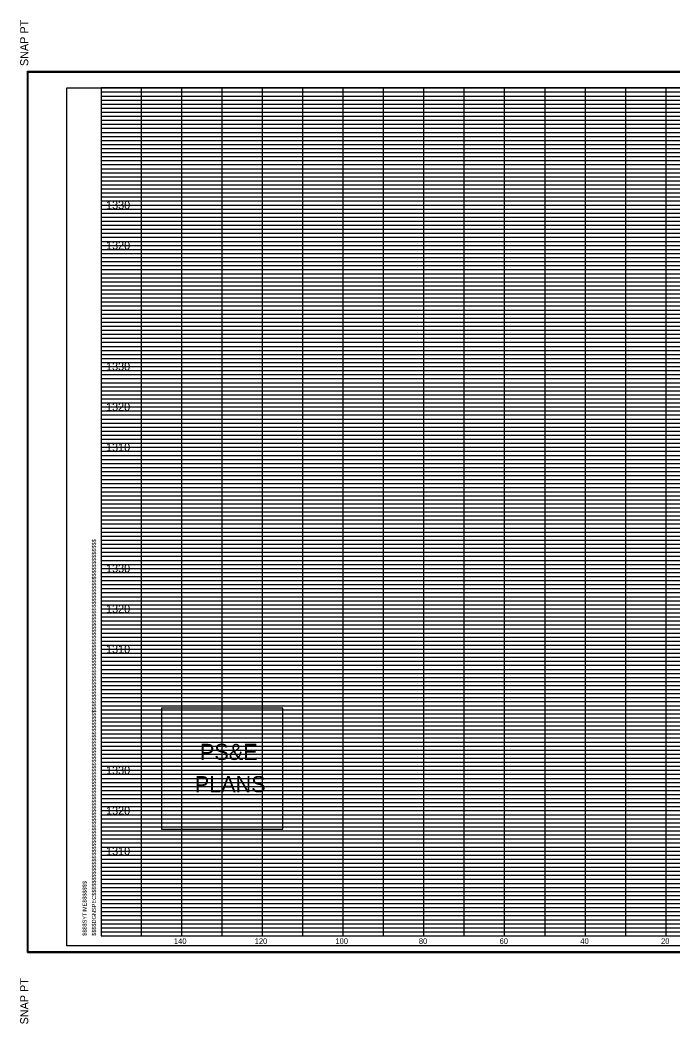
# Model space of a CAD drawing. Extents: x 980 to 1324, y 978 to 1227.
# Drawn here: x 979.9 to 1141.7, y 978.2 to 1226.8 of the extents above; entities that cross this region are included whole.
import ezdxf

# ---------------------------------------------------------------- set-up
doc = ezdxf.new("R2010")
doc.units = 0
for name, color, linetype in [('DESIGN - SHEET - Corner Text', 7, 'Continuous'), ('DESIGN - SHEET - Light Grid', 7, 'Continuous'), ('DESIGN - SHEET - Linework', 7, 'Continuous'), ('DESIGN - SHEET - Plot Shape', 7, 'Continuous'), ('DESIGN - TYPICAL - Finished Grade and Subgrade', 7, 'Continuous')]:
    doc.layers.add(name, color=color, linetype=linetype)

# ---------------------------------------------------------------- blocks, each defined once
blk = doc.blocks.new('XSTSHT')
at = {"layer": 'DESIGN - SHEET - Light Grid'}
for p, q in [((0, 20.9), (8, 20.9)), ((8, 20.9), (16, 20.9)), ((0, 20.8), (8, 20.8)), ((0, 20.7), (8, 20.7)), ((8, 20.8), (16, 20.8)), ((8, 20.7), (16, 20.7)), ((0, 20.6), (8, 20.6)), ((0, 20.5), (8, 20.5)), ((0, 20.4), (8, 20.4)), ((8, 20.6), (16, 20.6)), ((8, 20.5), (16, 20.5)), ((8, 20.4), (16, 20.4)), ((0, 20.3), (8, 20.3)), ((0, 20.2), (8, 20.2)), ((8, 20.3), (16, 20.3)), ((8, 20.2), (16, 20.2)), ((0, 20.1), (8, 20.1)), ((0, 19.9), (8, 19.9)), ((8, 20.1), (16, 20.1)), ((8, 19.9), (16, 19.9)), ((0, 19.8), (8, 19.8)), ((0, 19.7), (8, 19.7)), ((8, 19.8), (16, 19.8)), ((8, 19.7), (16, 19.7)), ((0, 19.6), (8, 19.6)), ((0, 19.5), (8, 19.5)), ((0, 19.4), (8, 19.4)), ((8, 19.6), (16, 19.6)), ((8, 19.5), (16, 19.5)), ((8, 19.4), (16, 19.4)), ((0, 19.3), (8, 19.3)), ((0, 19.2), (8, 19.2)), ((8, 19.3), (16, 19.3)), ((8, 19.2), (16, 19.2)), ((0, 19.1), (8, 19.1)), ((0, 18.9), (8, 18.9)), ((8, 19.1), (16, 19.1)), ((8, 18.9), (16, 18.9)), ((0, 18.8), (8, 18.8)), ((0, 18.7), (8, 18.7)), ((8, 18.8), (16, 18.8)), ((8, 18.7), (16, 18.7)), ((0, 18.6), (8, 18.6)), ((0, 18.5), (8, 18.5)), ((0, 18.4), (8, 18.4)), ((8, 18.6), (16, 18.6)), ((8, 18.5), (16, 18.5)), ((8, 18.4), (16, 18.4)), ((0, 18.3), (8, 18.3)), ((0, 18.2), (8, 18.2)), ((8, 18.3), (16, 18.3)), ((8, 18.2), (16, 18.2)), ((0, 18.1), (8, 18.1)), ((8, 18.1), (16, 18.1)), ((0, 17.9), (8, 17.9)), ((0, 17.8), (8, 17.8)), ((0, 17.7), (8, 17.7)), ((8, 17.9), (16, 17.9)), ((8, 17.8), (16, 17.8)), ((8, 17.7), (16, 17.7)), ((0, 17.6), (8, 17.6)), ((0, 17.5), (8, 17.5)), ((8, 17.6), (16, 17.6)), ((8, 17.5), (16, 17.5)), ((0, 17.4), (8, 17.4)), ((0, 17.3), (8, 17.3)), ((0, 17.2), (8, 17.2)), ((8, 17.4), (16, 17.4)), ((8, 17.3), (16, 17.3)), ((8, 17.2), (16, 17.2)), ((0, 17.1), (8, 17.1)), ((8, 17.1), (16, 17.1)), ((0, 16.9), (8, 16.9)), ((0, 16.8), (8, 16.8)), ((0, 16.7), (8, 16.7)), ((8, 16.9), (16, 16.9)), ((8, 16.8), (16, 16.8)), ((8, 16.7), (16, 16.7)), ((0, 16.6), (8, 16.6)), ((0, 16.5), (8, 16.5)), ((8, 16.6), (16, 16.6)), ((8, 16.5), (16, 16.5)), ((0, 16.4), (8, 16.4)), ((0, 16.3), (8, 16.3)), ((0, 16.2), (8, 16.2)), ((8, 16.4), (16, 16.4)), ((8, 16.3), (16, 16.3)), ((8, 16.2), (16, 16.2)), ((0, 16.1), (8, 16.1)), ((8, 16.1), (16, 16.1)), ((0, 15.9), (8, 15.9)), ((0, 15.8), (8, 15.8)), ((0, 15.7), (8, 15.7)), ((8, 15.9), (16, 15.9)), ((8, 15.8), (16, 15.8)), ((8, 15.7), (16, 15.7)), ((0, 15.6), (8, 15.6)), ((0, 15.5), (8, 15.5)), ((8, 15.6), (16, 15.6)), ((8, 15.5), (16, 15.5)), ((0, 15.4), (8, 15.4)), ((0, 15.3), (8, 15.3)), ((0, 15.2), (8, 15.2)), ((8, 15.4), (16, 15.4)), ((8, 15.3), (16, 15.3)), ((8, 15.2), (16, 15.2)), ((0, 15.1), (8, 15.1)), ((8, 15.1), (16, 15.1)), ((0, 14.9), (8, 14.9)), ((0, 14.8), (8, 14.8)), ((0, 14.7), (8, 14.7)), ((8, 14.9), (16, 14.9)), ((8, 14.8), (16, 14.8)), ((8, 14.7), (16, 14.7)), ((0, 14.6), (8, 14.6)), ((0, 14.5), (8, 14.5)), ((8, 14.6), (16, 14.6)), ((8, 14.5), (16, 14.5)), ((0, 14.4), (8, 14.4)), ((0, 14.3), (8, 14.3)), ((0, 14.2), (8, 14.2)), ((8, 14.4), (16, 14.4)), ((8, 14.3), (16, 14.3)), ((8, 14.2), (16, 14.2)), ((0, 14.1), (8, 14.1)), ((8, 14.1), (16, 14.1)), ((0, 13.9), (8, 13.9)), ((0, 13.8), (8, 13.8)), ((0, 13.7), (8, 13.7)), ((8, 13.9), (16, 13.9)), ((8, 13.8), (16, 13.8)), ((8, 13.7), (16, 13.7)), ((0, 13.6), (8, 13.6)), ((0, 13.5), (8, 13.5)), ((8, 13.6), (16, 13.6)), ((8, 13.5), (16, 13.5)), ((0, 13.4), (8, 13.4)), ((0, 13.3), (8, 13.3)), ((0, 13.2), (8, 13.2)), ((8, 13.4), (16, 13.4)), ((8, 13.3), (16, 13.3)), ((8, 13.2), (16, 13.2)), ((0, 13.1), (8, 13.1)), ((8, 13.1), (16, 13.1)), ((0, 12.9), (8, 12.9)), ((0, 12.8), (8, 12.8)), ((0, 12.7), (8, 12.7)), ((8, 12.9), (16, 12.9)), ((8, 12.8), (16, 12.8)), ((8, 12.7), (16, 12.7)), ((0, 12.6), (8, 12.6)), ((0, 12.5), (8, 12.5)), ((8, 12.6), (16, 12.6)), ((8, 12.5), (16, 12.5)), ((0, 12.4), (8, 12.4)), ((0, 12.3), (8, 12.3)), ((0, 12.2), (8, 12.2)), ((8, 12.4), (16, 12.4)), ((8, 12.3), (16, 12.3)), ((8, 12.2), (16, 12.2)), ((0, 12.1), (8, 12.1)), ((8, 12.1), (16, 12.1)), ((0, 11.9), (8, 11.9)), ((0, 11.8), (8, 11.8)), ((0, 11.7), (8, 11.7)), ((8, 11.9), (16, 11.9)), ((8, 11.8), (16, 11.8)), ((8, 11.7), (16, 11.7)), ((0, 11.6), (8, 11.6)), ((0, 11.5), (8, 11.5)), ((8, 11.6), (16, 11.6)), ((8, 11.5), (16, 11.5)), ((0, 11.4), (8, 11.4)), ((0, 11.3), (8, 11.3)), ((0, 11.2), (8, 11.2)), ((8, 11.4), (16, 11.4)), ((8, 11.3), (16, 11.3)), ((8, 11.2), (16, 11.2)), ((0, 11.1), (8, 11.1)), ((8, 11.1), (16, 11.1)), ((0, 10.9), (8, 10.9)), ((0, 10.8), (8, 10.8)), ((0, 10.7), (8, 10.7)), ((8, 10.9), (16, 10.9)), ((8, 10.8), (16, 10.8)), ((8, 10.7), (16, 10.7)), ((0, 10.6), (8, 10.6)), ((0, 10.5), (8, 10.5)), ((8, 10.6), (16, 10.6)), ((8, 10.5), (16, 10.5)), ((0, 10.4), (8, 10.4)), ((0, 10.3), (8, 10.3)), ((0, 10.2), (8, 10.2)), ((8, 10.4), (16, 10.4)), ((8, 10.3), (16, 10.3)), ((8, 10.2), (16, 10.2)), ((0, 10.1), (8, 10.1)), ((8, 10.1), (16, 10.1)), ((0, 9.9), (8, 9.9)), ((0, 9.8), (8, 9.8)), ((0, 9.7), (8, 9.7)), ((8, 9.9), (16, 9.9)), ((8, 9.8), (16, 9.8)), ((8, 9.7), (16, 9.7)), ((0, 9.6), (8, 9.6)), ((0, 9.5), (8, 9.5)), ((8, 9.6), (16, 9.6)), ((8, 9.5), (16, 9.5)), ((0, 9.4), (8, 9.4)), ((0, 9.3), (8, 9.3)), ((0, 9.2), (8, 9.2)), ((8, 9.4), (16, 9.4)), ((8, 9.3), (16, 9.3)), ((8, 9.2), (16, 9.2)), ((0, 9.1), (8, 9.1)), ((8, 9.1), (16, 9.1)), ((0, 8.9), (8, 8.9)), ((0, 8.8), (8, 8.8)), ((8, 8.9), (16, 8.9)), ((8, 8.8), (16, 8.8)), ((0, 8.7), (8, 8.7)), ((0, 8.6), (8, 8.6)), ((0, 8.5), (8, 8.5)), ((8, 8.7), (16, 8.7)), ((8, 8.6), (16, 8.6)), ((8, 8.5), (16, 8.5)), ((0, 8.4), (8, 8.4)), ((0, 8.3), (8, 8.3)), ((8, 8.4), (16, 8.4)), ((8, 8.3), (16, 8.3)), ((0, 8.2), (8, 8.2)), ((0, 8.1), (8, 8.1)), ((8, 8.2), (16, 8.2)), ((8, 8.1), (16, 8.1)), ((0, 7.9), (8, 7.9)), ((0, 7.8), (8, 7.8)), ((8, 7.9), (16, 7.9)), ((8, 7.8), (16, 7.8)), ((0, 7.7), (8, 7.7)), ((0, 7.6), (8, 7.6)), ((0, 7.5), (8, 7.5)), ((8, 7.7), (16, 7.7)), ((8, 7.6), (16, 7.6)), ((8, 7.5), (16, 7.5)), ((0, 7.4), (8, 7.4)), ((0, 7.3), (8, 7.3)), ((8, 7.4), (16, 7.4)), ((8, 7.3), (16, 7.3)), ((0, 7.2), (8, 7.2)), ((0, 7.1), (8, 7.1)), ((8, 7.2), (16, 7.2)), ((8, 7.1), (16, 7.1)), ((0, 6.9), (8, 6.9)), ((0, 6.8), (8, 6.8)), ((8, 6.9), (16, 6.9)), ((8, 6.8), (16, 6.8)), ((0, 6.7), (8, 6.7)), ((0, 6.6), (8, 6.6)), ((0, 6.5), (8, 6.5)), ((8, 6.7), (16, 6.7)), ((8, 6.6), (16, 6.6)), ((8, 6.5), (16, 6.5)), ((0, 6.4), (8, 6.4)), ((0, 6.3), (8, 6.3)), ((8, 6.4), (16, 6.4)), ((8, 6.3), (16, 6.3)), ((0, 6.2), (8, 6.2)), ((0, 6.1), (8, 6.1)), ((8, 6.2), (16, 6.2)), ((8, 6.1), (16, 6.1)), ((0, 5.9), (8, 5.9)), ((0, 5.8), (8, 5.8)), ((8, 5.9), (16, 5.9)), ((8, 5.8), (16, 5.8)), ((0, 5.7), (8, 5.7)), ((0, 5.6), (8, 5.6)), ((0, 5.5), (8, 5.5)), ((8, 5.7), (16, 5.7)), ((8, 5.6), (16, 5.6)), ((8, 5.5), (16, 5.5)), ((0, 5.4), (8, 5.4)), ((0, 5.3), (8, 5.3)), ((8, 5.4), (16, 5.4)), ((8, 5.3), (16, 5.3)), ((0, 5.2), (8, 5.2)), ((0, 5.1), (8, 5.1)), ((8, 5.2), (16, 5.2)), ((8, 5.1), (16, 5.1)), ((0, 4.9), (8, 4.9)), ((0, 4.8), (8, 4.8)), ((8, 4.9), (16, 4.9)), ((8, 4.8), (16, 4.8)), ((0, 4.7), (8, 4.7)), ((0, 4.6), (8, 4.6)), ((0, 4.5), (8, 4.5)), ((8, 4.7), (16, 4.7)), ((8, 4.6), (16, 4.6)), ((8, 4.5), (16, 4.5)), ((0, 4.4), (8, 4.4)), ((0, 4.3), (8, 4.3)), ((8, 4.4), (16, 4.4)), ((8, 4.3), (16, 4.3)), ((0, 4.2), (8, 4.2)), ((0, 4.1), (8, 4.1)), ((8, 4.2), (16, 4.2)), ((8, 4.1), (16, 4.1)), ((0, 3.9), (8, 3.9)), ((0, 3.8), (8, 3.8)), ((8, 3.9), (16, 3.9)), ((8, 3.8), (16, 3.8)), ((0, 3.7), (8, 3.7)), ((0, 3.6), (8, 3.6)), ((0, 3.5), (8, 3.5)), ((8, 3.7), (16, 3.7)), ((8, 3.6), (16, 3.6)), ((8, 3.5), (16, 3.5)), ((0, 3.4), (8, 3.4)), ((0, 3.3), (8, 3.3)), ((8, 3.4), (16, 3.4)), ((8, 3.3), (16, 3.3)), ((0, 3.2), (8, 3.2)), ((0, 3.1), (8, 3.1)), ((8, 3.2), (16, 3.2)), ((8, 3.1), (16, 3.1)), ((0, 2.9), (8, 2.9)), ((0, 2.8), (8, 2.8)), ((8, 2.9), (16, 2.9)), ((8, 2.8), (16, 2.8)), ((0, 2.7), (8, 2.7)), ((0, 2.6), (8, 2.6)), ((0, 2.5), (8, 2.5)), ((8, 2.7), (16, 2.7)), ((8, 2.6), (16, 2.6)), ((8, 2.5), (16, 2.5)), ((0, 2.4), (8, 2.4)), ((0, 2.3), (8, 2.3)), ((8, 2.4), (16, 2.4)), ((8, 2.3), (16, 2.3)), ((0, 2.2), (8, 2.2)), ((0, 2.1), (8, 2.1)), ((8, 2.2), (16, 2.2)), ((8, 2.1), (16, 2.1)), ((0, 1.9), (8, 1.9)), ((0, 1.8), (8, 1.8)), ((8, 1.9), (16, 1.9)), ((8, 1.8), (16, 1.8)), ((0, 1.7), (8, 1.7)), ((0, 1.6), (8, 1.6)), ((0, 1.5), (8, 1.5)), ((8, 1.7), (16, 1.7)), ((8, 1.6), (16, 1.6)), ((8, 1.5), (16, 1.5)), ((0, 1.4), (8, 1.4)), ((0, 1.3), (8, 1.3)), ((8, 1.4), (16, 1.4)), ((8, 1.3), (16, 1.3)), ((0, 1.2), (8, 1.2)), ((0, 1.1), (8, 1.1)), ((8, 1.2), (16, 1.2)), ((8, 1.1), (16, 1.1)), ((0, 0.9), (8, 0.9)), ((0, 0.8), (8, 0.8)), ((8, 0.9), (16, 0.9)), ((8, 0.8), (16, 0.8)), ((0, 0.7), (8, 0.7)), ((0, 0.6), (8, 0.6)), ((0, 0.5), (8, 0.5)), ((8, 0.7), (16, 0.7)), ((8, 0.6), (16, 0.6)), ((8, 0.5), (16, 0.5)), ((0, 0.4), (8, 0.4)), ((0, 0.3), (8, 0.3)), ((8, 0.4), (16, 0.4)), ((8, 0.3), (16, 0.3)), ((0, 0.2), (8, 0.2)), ((0, 0.1), (8, 0.1)), ((8, 0.2), (16, 0.2)), ((8, 0.1), (16, 0.1))]:
    blk.add_line(p, q, dxfattribs=at)
at = {"layer": 'DESIGN - SHEET - Linework'}
for p, q in [((-1.823, -0.414), (-1.823, 21.414)), ((-1.823, 21.414), (32.217, 21.414)), ((1, 0), (1, 21)), ((2, 0), (2, 21)), ((3, 0), (3, 21)), ((4, 0), (4, 21)), ((5, 0), (5, 21)), ((6, 0), (6, 21)), ((7, 0), (7, 21)), ((8, 0), (8, 21)), ((9, 0), (9, 21)), ((10, 0), (10, 21)), ((11, 0), (11, 21)), ((12, 0), (12, 21)), ((13, 0), (13, 21)), ((14, 0), (14, 21)), ((0, 20), (28, 20)), ((0, 19), (32, 19)), ((0, 18), (32, 18)), ((0, 17), (32, 17)), ((0, 16), (32, 16)), ((0, 15), (32, 15)), ((0, 14), (32, 14)), ((0, 13), (32, 13)), ((0, 12), (32, 12)), ((0, 11), (32, 11)), ((0, 10), (32, 10)), ((0, 9), (32, 9)), ((0, 8), (32, 8)), ((0, 7), (32, 7)), ((0, 6), (32, 6)), ((0, 5), (32, 5)), ((0, 4), (32, 4)), ((0, 3), (32, 3)), ((0, 2), (32, 2)), ((0, 1), (32, 1)), ((-1.823, -0.414), (32.217, -0.414))]:
    blk.add_line(p, q, dxfattribs=at)
blk.add_lwpolyline([(0, 21), (0, 0), (32, 0), (32, 21), (0, 21)], dxfattribs=at)
at = {"layer": 'DESIGN - SHEET - Plot Shape'}
for points in [[(-1.803, 21.394), (32.197, 21.394), (32.197, -0.394), (-1.803, -0.394)], [(-0.85, 21), (32, 21), (32, -0.25), (-0.85, -0.25)]]:
    blk.add_lwpolyline(points, close=True, dxfattribs=at)
at = {"layer": 'DESIGN - SHEET - Corner Text'}
for s, height, p in [('  SNAP PT', 0.2, (-1.803, 21.394)), ('$$$$DGNSPEC$$$$$$$$$$$$$$$$$$$$$$$$$$$$$$$$$$$$$$$$$$$$$$$$$$$$$$$$$$$$$$$$$$$$$$$$$$$$$$$$$$$$$$$$$$$$$$$$$$$$$$$$$$$$$$$$$$$', 0.100002, (-0.126, 0)), ('$$$$SYTIME$$$$$$$', 0.1, (-0.358, 0)), ('SNAP PT  ', 0.2, (-1.803, -2.194))]:
    blk.add_text(s, height=height, rotation=90, dxfattribs=at).set_placement(p)

msp = doc.modelspace()

# ---------------------------------------------------------------- linework, layer by layer
at = {"layer": 'DESIGN - SHEET - Corner Text'}
msp.add_lwpolyline([(1015, 1056.38), (1015, 1026.38), (1045, 1026.38), (1045, 1056.38)], close=True, dxfattribs=at)

# ---------------------------------------------------------------- block references
at = {"layer": 'DESIGN - TYPICAL - Finished Grade and Subgrade', "xscale": 10, "yscale": 10}
msp.add_blockref('XSTSHT', (1000, 1000), dxfattribs=at)

# ---------------------------------------------------------------- texts
at = {"layer": 'DESIGN - SHEET - Corner Text'}
for s, height, p in [('1330', 2, (1001.25, 1180)), ('1320', 2, (1001.25, 1170)), ('1330', 2, (1001.25, 1140)), ('1320', 2, (1001.25, 1130)), ('1310', 2, (1001.25, 1120)), ('1330', 2, (1001.25, 1090)), ('1320', 2, (1001.25, 1080)), ('1310', 2, (1001.25, 1070)), ('PS&E', 4, (1024.52, 1043.56)), ('1330', 2, (1001.25, 1040)), ('PLANS', 4, (1023.23, 1035.56)), ('1320', 2, (1001.25, 1030)), ('1310', 2, (1001.25, 1020)), ('140', 1.4, (1018.06, 998)), ('120', 1.4, (1038.06, 998)), ('100', 1.4, (1058.06, 998)), ('80', 1.4, (1078.74, 998)), ('60', 1.4, (1098.74, 998)), ('40', 1.4, (1118.74, 998)), ('20', 1.4, (1138.74, 998))]:
    msp.add_text(s, height=height, dxfattribs=at).set_placement(p)

doc.saveas('drawing.dxf')
